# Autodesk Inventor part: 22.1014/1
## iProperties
Created: 2011-07
Part Number: 22.1014/1
Document SubType Name: Modeling
Designer: Administrator
Density: 1.06 g/cm^3
Material: ABS Plastic
Mass: 4.82994 g
Surface Area: 47.9346 cm^2
Volume: 4.55654 cm^3
Description: END CAP 90X19 GRAY
Vendor: S
Translation Standard: STEP AP203
FileName: 22-1014-1.stp
PreProcessor: Mechanical Desktop 2011
PostProcessor: Build: 236a, Release: 2009 RTM - Date: Fri 02/22/2008
Sent Units: MM
Uncertainty: 1.0000000000000002e-06
Author: Administrator
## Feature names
1. Base1
